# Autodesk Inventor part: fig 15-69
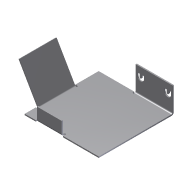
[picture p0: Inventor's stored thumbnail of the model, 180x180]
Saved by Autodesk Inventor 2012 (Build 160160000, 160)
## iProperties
Shininess: 77.0
Angle Display Precision: 2
Document Length Units: 11269
Document Angle Units: 11279
Document Time Units: 11290
Document Mass Units: 11283
Document Length Units Precision: 3
Document Angle Units Precision: 2
Created: 2002-04
Part Number: fig 15-69
Document SubType Name: Sheet Metal
Density: 1 g/cm^3
Sheet Metal Rule: Default
Material: Default
Density: 0.0
Volumn: 0.0
Area: 0.0
PropertySet Name: Model Information
Control State: 0
Master: False
Checked Out: False
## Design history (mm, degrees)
node "Face1"
  sketch "Sketch1"
    geometry: L1 (12.647, 25.882)-(12.647, -14.118); L2 (12.647, -14.118)-(-17.353, -14.118); L3 (-17.353, -14.118)-(-17.353, 15.882); L4 (-17.353, 15.882)-(-2.353, 15.882); L5 (-2.353, 15.882)-(-2.353, 25.882); L6 (-2.353, 25.882)-(12.647, 25.882); 1 further point
    constraints: 12 end point, 4 parallel, 1 perpendicular
    dimensions: "d5" = 30 distance of L2.end L3.end; "d6" = 10 distance of L4.end L5.end; "d7" = 15 distance of L3.end L4.end; "d25" = 15 distance of L5.end L1.start
sketch "Sketch3"
  geometry: L1 (10, -15)-(10, 0)
  constraints: 2 end point
feature "Fold3" sketch "Sketch3" dims "d26" = 0.5 (= BendRadius), "d27" = 90 deg, "d28" = 0.5 (= BendRadius), "d96" = 0.5 (= BendReliefWidth), "d97" = 0.25 (= BendReliefDepth), "d98" = 1 (= MinimumRemnant), "SeamGap" = 0.01, "Thickness" = 0.5
node "Flange2"
sketch "Sketch6"
  geometry: L1 (-6.914, 3.413)-(-5.843, 3.413); L2 (-5.843, 0.624)-(-6.914, 0.624); L3 (-6.914, 2.432)-(-5.843, 2.432); L4 (-5.843, 1.605)-(-6.914, 1.605); L5 (-6.914, 0.624)-(-6.914, 1.605); L6 (-6.914, 2.432)-(-6.914, 3.413); L7 (-6.914, 12.568)-(-6.914, 11.587); L8 (-6.914, 14.376)-(-6.914, 13.395); L9 (-6.914, 11.587)-(-5.843, 11.587); L10 (-5.843, 14.376)-(-6.914, 14.376); L11 (-6.914, 12.568)-(-5.843, 12.568); L12 (-5.843, 13.395)-(-6.914, 13.395); A1 r 1.394 centre (-5.843, 2.018) between (-5.843, 0.624) and (-5.843, 3.413); A2 r 0.413 centre (-5.843, 2.018) between (-5.843, 1.605) and (-5.843, 2.432); A3 r 1.394 centre (-5.843, 12.982) between (-5.843, 11.587) and (-5.843, 14.376); A4 r 0.413 centre (-5.843, 12.982) between (-5.843, 12.568) and (-5.843, 13.395)
  constraints: 24 end point, 8 point on circle, 4 centre point, 3 equal length, 1 perpendicular
cut "Cut1" sketch "Sketch6" dims "d49" = 0.5 (= Thickness), "d50" = 0
node "Flange3"
body "Solid1"
face "Plate1" dims "Thickness" = 0.5
sketch "Sketch5"
  geometry: L1 (20, 0)-(5, 0); L2 (5, 0)-(5, 15); L3 (5, 15)-(20, 15); L4 (20, 15)-(20, 0)
  constraints: 8 end point
face "Plate6" dims "d35" = 10, "d36" = 5, "d38" = 15, "d39" = 60 deg, "d40" = 0.5 (= BendRadius), "Thickness" = 0.5, "MinimumRemnant" = 1 (= 2 x Thickness), "BendReliefWidth" = 0.5 (= Thickness)
bend "Bend5" dims "d38" = 15, "d39" = 60 deg, "d40" = 0.5 (= BendRadius), "d99" = 0.5 (= BendReliefWidth), "d100" = 0.25 (= BendReliefDepth), "d101" = 1 (= MinimumRemnant), "SeamGap" = 0.01, "Thickness" = 0.5, "MinimumRemnant" = 1 (= 2 x Thickness), "BendReliefWidth" = 0.5 (= Thickness), "TransitionRadius" = 0.5 (= BendRadius)
sketch "Sketch7"
  geometry: L1 (25, 0)-(15, 0); L2 (15, 0)-(15, 5); L3 (15, 5)-(25, 5); L4 (25, 5)-(25, 0)
  constraints: 8 end point
face "Plate7" dims "d57" = 5, "d58" = 10, "d60" = 5, "d61" = 90 deg, "d62" = 0.5 (= BendRadius), "Thickness" = 0.5, "MinimumRemnant" = 1 (= 2 x Thickness), "BendReliefWidth" = 0.5 (= Thickness)
bend "Bend7" dims "d59" = 0.5 (= BendRadius), "d60" = 5, "d61" = 90 deg, "d62" = 0.5 (= BendRadius), "d102" = 0.5 (= BendReliefWidth), "d103" = 0.25 (= BendReliefDepth), "d104" = 1 (= MinimumRemnant), "SeamGap" = 0.01, "Thickness" = 0.5, "MinimumRemnant" = 1 (= 2 x Thickness), "BendReliefWidth" = 0.5 (= Thickness)
other parameters: "BendRadius" = 0.5 (= Thickness), "BendReliefDepth" = 0.25 (= 0.5 x Thickness), "CornerReliefSize" = 2 (= 4 x Thickness), "d0" = 0.5 (= BendRadius), "d13" = 0.5 (= BendRadius), "d31" = 0.5 (= BendRadius), "d37" = 0.5 (= BendRadius), "JacobiRadiusSize" = 0.5 (= Thickness), "GapSize" = 0.5 (= Thickness)
